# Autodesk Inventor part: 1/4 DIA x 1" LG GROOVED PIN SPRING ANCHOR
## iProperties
Title: 1/4 DIA x 1" LG GROOVED PIN SPRING ANCHOR
Author: ERG
Created: 2001-10
Part Number: Grooved Pin Type G
Document SubType Name: Modeling
Designer: ERG
Mfg: DRIV-LOK
Mfg Part No: 1/4 DIA x 1" LG
Control State: 0
Master: False
Checked Out: False
Last Check In By: ERG
Last Check In Date: 2001-10-10
PropertySet Name: Design Tracking Control
Shininess: 64.0
Angle Display Precision: 2
Document Length Units: 11272
Document Angle Units: 11286
Document Time Units: 11279
Document Mass Units: 11290
Document Length Units Precision: 3
Document Angle Units Precision: 2
Compacted: True
PropertySet Name: _Private Model Information
Density: 0.0
Volumn: 0.0
Area: 0.0
PropertySet Name: Model Information
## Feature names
1. Extrusion1
2. Revolution1
3. Extrusion2
4. Extrusion3
5. Circular Pattern1
6. Revolution2
7. Revolution3
